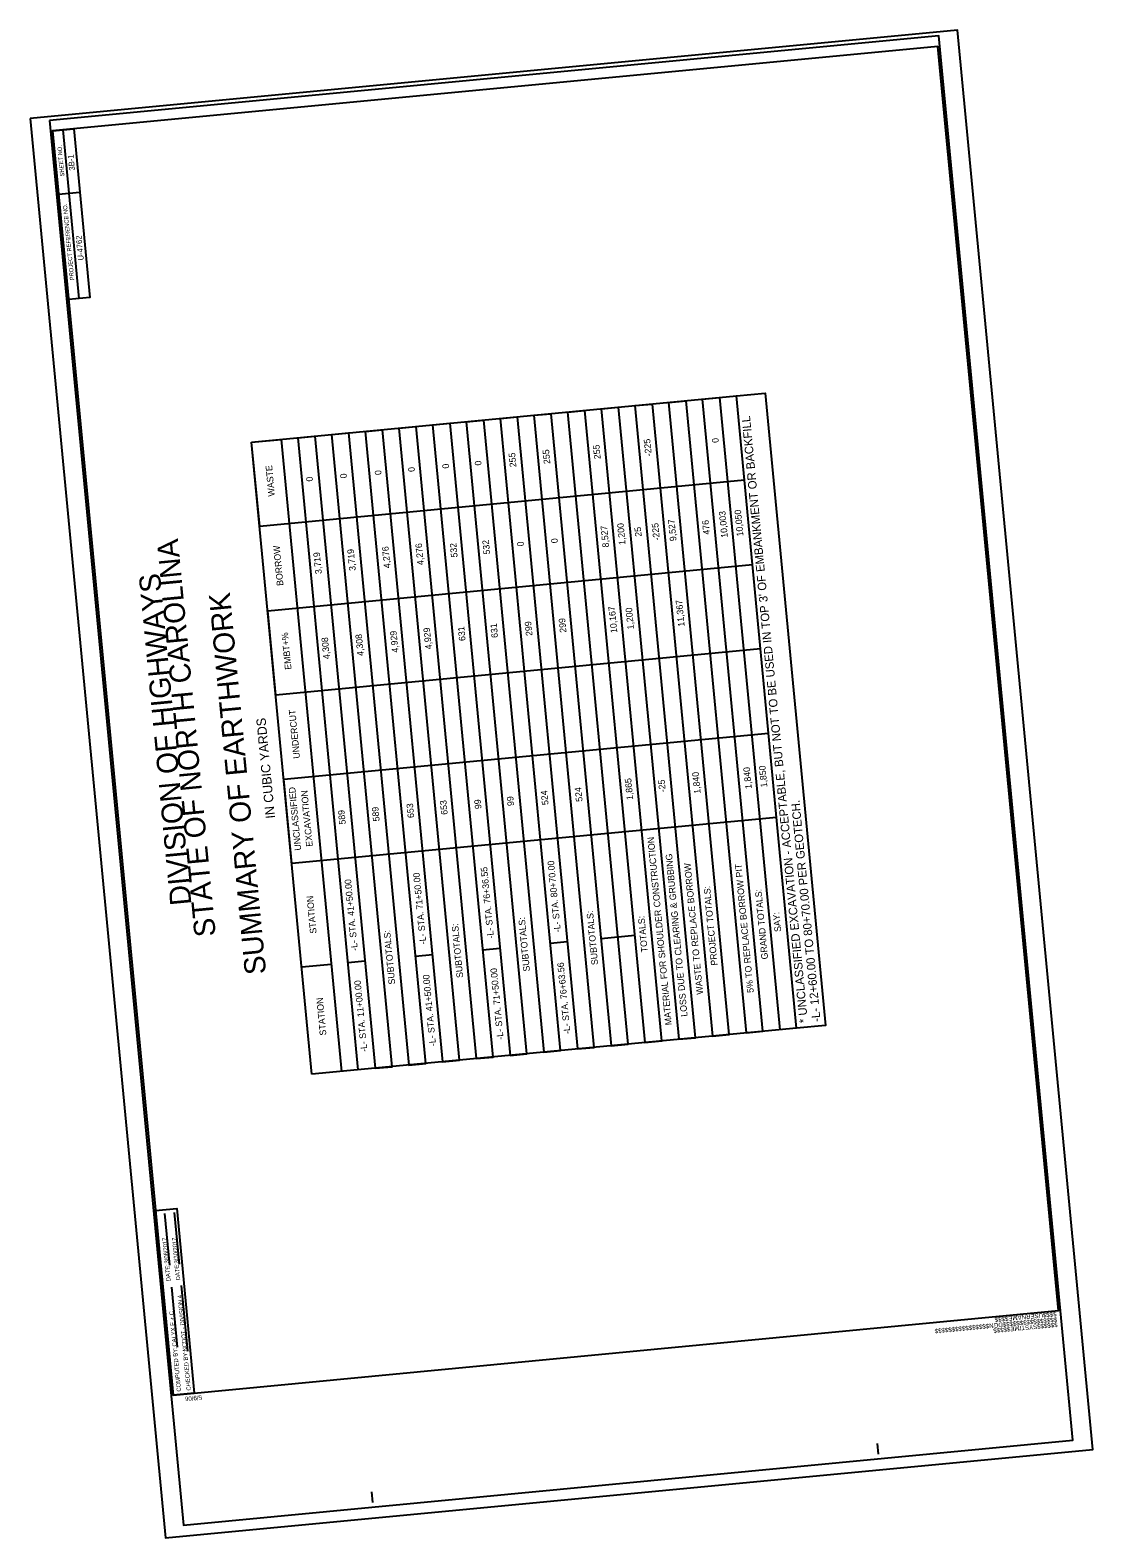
# Model space of a CAD drawing. Extents: x 2368038 to 2369293, y 804313 to 806094.
import ezdxf

# ---------------------------------------------------------------- set-up
doc = ezdxf.new("R2010")
doc.units = 0
for name, color, linetype in [('Sheet Cutting Line CELL', 7, 'Continuous'), ('Sheet Data Field CELL', 7, 'Continuous'), ('Sheet Plot Border Inside CELL', 7, 'Continuous'), ('Sheet Plot Border Outside CELL', 7, 'Continuous'), ('Sheet Summary Earthwork CELL', 7, 'Continuous')]:
    doc.layers.add(name, color=color, linetype=linetype)

msp = doc.modelspace()

# ---------------------------------------------------------------- linework, layer by layer
at = {"layer": 'Sheet Cutting Line CELL'}
for p, q in [((2369292.6, 804417.2), (2369132.7, 806093.6)), ((2368037.7, 805989.1), (2368197.6, 804312.8)), ((2368197.6, 804312.8), (2369292.6, 804417.2))]:
    msp.add_line(p, q, dxfattribs=at)
at = {"layer": 'Sheet Plot Border Inside CELL'}
msp.add_lwpolyline([(2368060.4, 805986.8), (2368218.7, 804327.8), (2369269, 804428), (2369110.8, 806087)], close=True, dxfattribs=at)
at = {"layer": 'Sheet Plot Border Outside CELL'}
msp.add_lwpolyline([(2368037.7, 805989.1), (2368197.6, 804312.8), (2369292.6, 804417.2), (2369132.7, 806093.6)], close=True, dxfattribs=at)
at = {"layer": 'Sheet Summary Earthwork CELL'}
for p, q in [((2368095.6, 805776.6), (2368076.7, 805975.8)), ((2368071.3, 805899.9), (2368096.2, 805902.3)), ((2368299.2, 805606.9), (2368871.6, 805661.5)), ((2368942.8, 804914.9), (2368871.6, 805661.5)), ((2368299.2, 805606.9), (2368334, 805610.2)), ((2368308.7, 805507.3), (2368299.2, 805606.9)), ((2368370.4, 804860.3), (2368299.2, 805606.9)), ((2368334, 805610.2), (2368405.3, 804863.6)), ((2368881.1, 805561.9), (2368308.7, 805507.3)), ((2368318.2, 805407.8), (2368890.6, 805462.4)), ((2368327.7, 805308.2), (2368318.2, 805407.8)), ((2368900.1, 805362.8), (2368327.7, 805308.2)), ((2368337.2, 805208.7), (2368909.6, 805263.3)), ((2368346.7, 805109.1), (2368337.2, 805208.7)), ((2368919.1, 805163.7), (2368346.7, 805109.1)), ((2368751.6, 805024.2), (2368711.8, 805020.4)), ((2368512.7, 805001.4), (2368492.8, 804999.5)), ((2368592.3, 805009), (2368572.4, 805007.1)), ((2368671.9, 805016.6), (2368652, 805014.7)), ((2368393.2, 804990), (2368358.4, 804986.7)), ((2368433, 804993.8), (2368413.1, 804991.9)), ((2368942.8, 804914.9), (2368370.4, 804860.3)), ((2368214, 804635.9), (2368208.2, 804697.1)), ((2368202.6, 804634.7), (2368196.7, 804695.8)), ((2368211.7, 804537.8), (2368204.9, 804609)), ((2368223.8, 804533.4), (2368216.5, 804610.8)), ((2369251.9, 804581.1), (2369251.9, 804581.1)), ((2369251.9, 804581.1), (2369251.9, 804581.1)), ((2369251.9, 804581.1), (2369251.9, 804581.1)), ((2369251.9, 804581.1), (2369251.9, 804581.1)), ((2369251.9, 804581.1), (2369251.9, 804581.1)), ((2369251.9, 804581.1), (2369251.9, 804581.1)), ((2369251.9, 804581.1), (2369251.9, 804581.1)), ((2369251.9, 804581.1), (2369251.9, 804581.1)), ((2369251.9, 804581.1), (2369251.9, 804581.1)), ((2369039.5, 804411.7), (2369038.3, 804424.1)), ((2368442.2, 804354.7), (2368441, 804367.1))]:
    msp.add_line(p, q, dxfattribs=at)
for points in [[(2368064.2, 805974.6), (2368206.6, 804481.4), (2369251.9, 804581.1), (2369109.4, 806074.3)], [(2368083.2, 805775.5), (2368064.2, 805974.6), (2368089.1, 805977), (2368108.1, 805777.8)], [(2368942.8, 804914.9), (2368871.6, 805661.5), (2368905.7, 805664.7), (2368976.9, 804918.1)], [(2368206.6, 804481.4), (2368185.8, 804699.4), (2368210.7, 804701.8), (2368231.5, 804483.8)]]:
    msp.add_lwpolyline(points, close=True, dxfattribs=at)
for points in [[(2368425.2, 804865.5), (2368354, 805612.1), (2368373.9, 805614), (2368445.1, 804867.4), (2368465, 804869.3), (2368393.8, 805615.9), (2368413.7, 805617.8), (2368484.9, 804871.2), (2368504.8, 804873.1), (2368433.6, 805619.7), (2368453.5, 805621.6), (2368524.7, 804875), (2368544.6, 804876.9), (2368473.4, 805623.5), (2368493.3, 805625.4), (2368564.5, 804878.8), (2368584.5, 804880.7), (2368513.2, 805627.3), (2368533.1, 805629.2), (2368604.4, 804882.6), (2368624.3, 804884.5), (2368553, 805631.1), (2368573, 805633), (2368644.2, 804886.4), (2368664.1, 804888.3), (2368592.9, 805634.9), (2368612.8, 805636.8), (2368684, 804890.2), (2368703.9, 804892.1), (2368632.7, 805638.7), (2368652.6, 805640.6), (2368723.8, 804894), (2368743.7, 804895.9), (2368672.5, 805642.5), (2368692.4, 805644.4), (2368763.6, 804897.8), (2368783.5, 804899.7), (2368712.3, 805646.3), (2368732.2, 805648.2), (2368803.5, 804901.6), (2368823.4, 804903.5), (2368752.1, 805650.1), (2368772.1, 805652), (2368843.3, 804905.4), (2368863.2, 804907.3), (2368792, 805653.9), (2368811.9, 805655.8), (2368883.1, 804909.2), (2368903, 804911.1), (2368831.8, 805657.7), (2368851.7, 805659.6), (2368922.9, 804913)], [(2369248.3, 804618.4), (2369248.3, 804618.4)]]:
    msp.add_lwpolyline(points, dxfattribs=at)

# ---------------------------------------------------------------- texts
at = {"layer": 'Sheet Data Field CELL'}
for s, height, p in [('3B-1', 6.75, (2368090.6, 805928.1)), ('U-4762', 6.75, (2368101, 805821.9)), (' 3/06/2017', 5, (2368201.7, 804635.2)), ('3/30/2017', 5, (2368213, 804637.1)), ('NCDOT - DIVISION 4', 5, (2368223, 804533.3)), (' CALYX E + C', 5, (2368210.9, 804537.1))]:
    msp.add_text(s, height=height, rotation=95.4494, dxfattribs=at).set_placement(p)
at = {"layer": 'Sheet Summary Earthwork CELL'}
for s, height, rotation, p in [('SHEET NO.', 5, 95.4494, (2368078.1, 805921)), ('PROJECT REFERENCE NO.', 5, 95.4494, (2368089.7, 805798.4)), ("* UNCLASSIFIED EXCAVATION - ACCEPTABLE, BUT NOT TO BE USED IN TOP 3' OF EMBANKMENT OR BACKFILL", 10, 95.4494, (2368956.1, 804921.3)), ('-225', 7.75, 95.4494, (2368771.8, 805590.6)), ('0', 7.75, 95.4494, (2368850.9, 805606.5)), ('255', 7.75, 95.4494, (2368611.9, 805577.7)), ('255', 7.75, 95.4494, (2368652, 805581.5)), ('255', 7.75, 95.4494, (2368711.5, 805587.2)), ('WASTE', 7.75, 95.4494, (2368326.8, 805543.3)), ('0', 7.75, 95.4494, (2368411.8, 805564.6)), ('0', 7.75, 95.4494, (2368452.7, 805568.5)), ('0', 7.75, 95.4494, (2368492.1, 805572.2)), ('0', 7.75, 95.4494, (2368532.5, 805576.1)), ('0', 7.75, 95.4494, (2368570.8, 805579.7)), ('0', 7.75, 95.4494, (2368371.7, 805560.8)), ('10,003', 7.75, 95.4494, (2368861.6, 805494.4)), ('10,050', 7.75, 95.4494, (2368880, 805496)), ('8,527', 7.75, 95.4494, (2368721.4, 805482.9)), ('1,200', 7.75, 95.4494, (2368740.8, 805485.9)), ('25', 7.75, 95.4494, (2368759.9, 805495.7)), ('-225', 7.75, 95.4494, (2368781.3, 805491.2)), ('9,527', 7.75, 95.4494, (2368801, 805490.4)), ('476', 7.75, 95.4494, (2368840.4, 805498.1)), ('STATE OF NORTH CAROLINA', 25, 95.4494, (2368256.9, 805023.8)), ('BORROW', 7.75, 95.4494, (2368336.8, 805437.6)), ('3,719', 7.75, 95.4494, (2368422.2, 805455.3)), ('4,276', 7.75, 95.4494, (2368463.2, 805458.4)), ('4,276', 7.75, 95.4494, (2368502.6, 805462.1)), ('532', 7.75, 95.4494, (2368542.5, 805471)), ('532', 7.75, 95.4494, (2368580.9, 805474.6)), ('0', 7.75, 95.4494, (2368620.8, 805484.2)), ('0', 7.75, 95.4494, (2368660.9, 805488)), ('3,719', 7.75, 95.4494, (2368382.1, 805451.5)), ('DIVISION OF HIGHWAYS', 25, 95.4494, (2368228.2, 805060.9)), ('SUMMARY OF EARTHWORK', 25, 95.4494, (2368316.4, 804979.2)), ('10,167', 7.75, 95.4494, (2368731.1, 805381.9)), ('1,200', 7.75, 95.4494, (2368750.8, 805386.1)), ('11,367', 7.75, 95.4494, (2368810.6, 805389.4)), ('631', 7.75, 95.4494, (2368590.3, 805376.1)), ('299', 7.75, 95.4494, (2368630.9, 805378.5)), ('299', 7.75, 95.4494, (2368671, 805382.3)), ('EMBT+%', 7.75, 95.4494, (2368346.3, 805338.6)), ('4,308', 7.75, 95.4494, (2368391.7, 805351)), ('4,308', 7.75, 95.4494, (2368431.8, 805354.8)), ('4,929', 7.75, 95.4494, (2368472.7, 805358.7)), ('4,929', 7.75, 95.4494, (2368512.1, 805362.5)), ('631', 7.75, 95.4494, (2368551.9, 805372.5)), ('UNDERCUT', 7.75, 95.4494, (2368356.3, 805233.5)), ('IN CUBIC YARDS', 11, 95.4494, (2368326.9, 805162.9)), ('1,840', 7.75, 95.4494, (2368829.5, 805192)), ('1,840', 7.75, 95.4494, (2368889.9, 805197.7)), ('1,850', 7.75, 95.4494, (2368908.3, 805199.5)), ('UNCLASSIFIED', 7.75, 95.4494, (2368357.8, 805124.9)), ('EXCAVATION', 7.75, 95.4494, (2368371.4, 805129.6)), ('524', 7.75, 95.4494, (2368649.9, 805178.7)), ('524', 7.75, 95.4494, (2368690, 805182.6)), ('1,865', 7.75, 95.4494, (2368749.9, 805184.6)), ('-25', 7.75, 95.4494, (2368788.3, 805193.8)), ('653', 7.75, 95.4494, (2368491.3, 805163.4)), ('653', 7.75, 95.4494, (2368530.8, 805167.2)), ('99', 7.75, 95.4494, (2368570.8, 805173.9)), ('99', 7.75, 95.4494, (2368609.2, 805177.6)), ('-L- 12+60.00 TO 80+70.00 PER GEOTECH.', 10, 95.4494, (2368971.1, 804922.7)), ('589', 7.75, 95.4494, (2368410.4, 805155.6)), ('589', 7.75, 95.4494, (2368450.4, 805159.4)), ('MATERIAL FOR SHOULDER CONSTRUCTION', 7.75, 95.4494, (2368795.4, 804918.6)), ('-L- STA. 80+70.00', 7.75, 95.4494, (2368664.3, 805028.4)), ('LOSS DUE TO CLEARING & GRUBBING', 7.75, 95.4494, (2368814, 804928.7)), ('WASTE TO REPLACE BORROW', 7.75, 95.4494, (2368832.4, 804954.8)), ('5% TO REPLACE BORROW PIT', 7.75, 95.4494, (2368892.2, 804956.8)), ('-L- STA. 41+50.00', 7.75, 95.4494, (2368424.6, 805006.5)), ('-L- STA. 71+50.00', 7.75, 95.4494, (2368505.6, 805014.2)), ('-L- STA. 76+36.55', 7.75, 95.4494, (2368585.4, 805021)), ('STATION', 7.75, 95.4494, (2368376, 805026.8)), ('PROJECT TOTALS:', 7.75, 95.4494, (2368849.5, 804989.1)), ('GRAND TOTALS:', 7.75, 95.4494, (2368909.1, 804996.4)), ('SUBTOTALS:', 7.75, 95.4494, (2368708.4, 804989.7)), ('SUBTOTALS:', 7.75, 95.4494, (2368549.1, 804974.5)), ('SUBTOTALS:', 7.75, 95.4494, (2368627.9, 804982)), ('TOTALS:', 7.75, 95.4494, (2368767.1, 805004.8)), ('SAY:', 7.75, 95.4494, (2368924.6, 805028.8)), ('SUBTOTALS:', 7.75, 95.4494, (2368468.8, 804966.8)), ('-L- STA. 71+50.00', 7.75, 95.4494, (2368596.8, 804901.5)), ('-L- STA. 76+63.56', 7.75, 95.4494, (2368675.8, 804908.2)), ('-L- STA. 11+00.00', 7.75, 95.4494, (2368436, 804887.1)), ('-L- STA. 41+50.00', 7.75, 95.4494, (2368517, 804893.9)), ('STATION', 7.75, 95.4494, (2368387.5, 804906.5)), ('DATE:', 5, 95.4494, (2368203.6, 804616)), ('DATE:', 5, 95.4494, (2368214.9, 804617.1)), ('$$$$$$$$$$$$$$$$DGN$$$$$$$$$$$$$$$$', 5.25, 185.4494, (2369250.2, 804573.3)), ('$$$$USERNAME$$$$', 5.25, 185.4494, (2369249.6, 804579.8)), ('$$$$$$SYSTIME$$$$$', 5.25, 185.4494, (2369250.8, 804567.2)), ('COMPUTED BY:', 5, 95.4494, (2368215.9, 804485.7)), ('CHECKED BY:', 5, 95.4494, (2368227.5, 804486.9)), ('5/9/06', 5.25, 185.4494, (2368240.3, 804481.3))]:
    msp.add_text(s, height=height, rotation=rotation, dxfattribs=at).set_placement(p)

doc.saveas('drawing.dxf')
